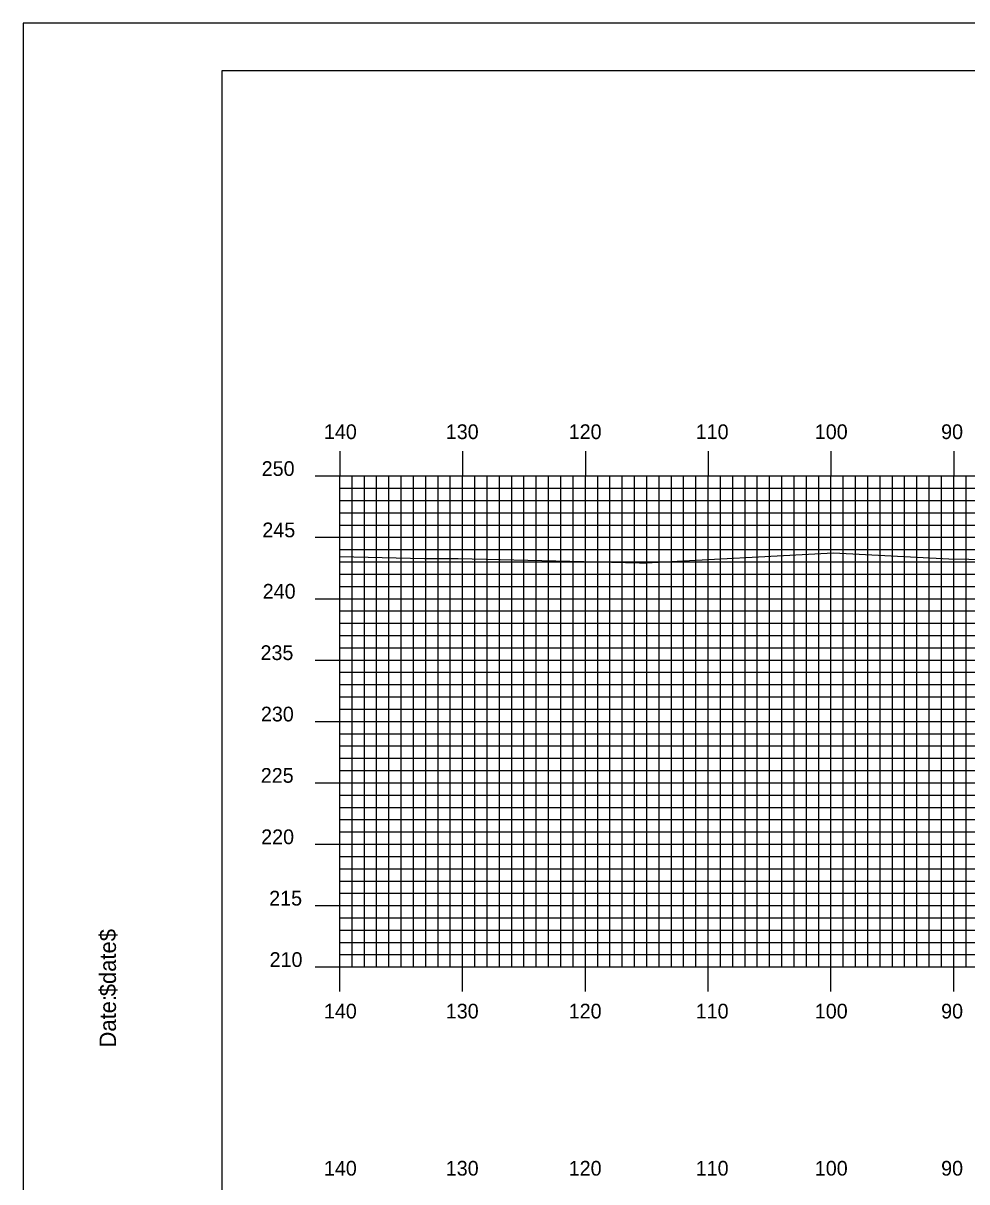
# Model space of a CAD drawing. Extents: x 1816489 to 1816833, y 442591 to 442811.
# Drawn here: x 1816489.3 to 1816566.1, y 442716.2 to 442810.5 of the extents above; entities that cross this region are included whole.
import ezdxf

# ---------------------------------------------------------------- set-up
doc = ezdxf.new("R2010")
doc.units = 0
for name, color, linetype in [('BORDER', 7, 'Continuous'), ('H_V ANNOTATION', 7, 'Continuous'), ('MAJOR', 7, 'Continuous'), ('MINOR', 7, 'Continuous'), ('PLOT BOUNDARY', 7, 'Continuous'), ('S_Roadway_Centerline', 7, 'Continuous')]:
    doc.layers.add(name, color=color, linetype=linetype)

msp = doc.modelspace()

# ---------------------------------------------------------------- linework, layer by layer
at = {"layer": 'BORDER'}
msp.add_lwpolyline([(1816505.473, 442596.665), (1816825.473, 442596.665), (1816825.473, 442806.665), (1816505.473, 442806.665)], close=True, dxfattribs=at)
at = {"layer": 'MAJOR'}
for p, q in [((1816515.073, 442775.669), (1816515.073, 442773.665)), ((1816525.073, 442775.669), (1816525.073, 442773.665)), ((1816535.073, 442775.669), (1816535.073, 442773.665)), ((1816545.073, 442775.669), (1816545.073, 442773.665)), ((1816555.073, 442775.669), (1816555.073, 442773.665)), ((1816565.073, 442775.669), (1816565.073, 442773.665)), ((1816513.069, 442773.665), (1816515.073, 442773.665)), ((1816515.073, 442773.665), (1816795.073, 442773.665)), ((1816515.073, 442733.665), (1816515.073, 442773.665)), ((1816515.073, 442733.665), (1816515.073, 442773.665)), ((1816515.073, 442773.665), (1816795.073, 442773.665)), ((1816525.073, 442733.665), (1816525.073, 442773.665)), ((1816535.073, 442733.665), (1816535.073, 442773.665)), ((1816545.073, 442733.665), (1816545.073, 442773.665)), ((1816555.073, 442733.665), (1816555.073, 442773.665)), ((1816565.073, 442733.665), (1816565.073, 442773.665)), ((1816513.069, 442768.665), (1816515.073, 442768.665)), ((1816515.073, 442768.665), (1816795.073, 442768.665)), ((1816513.069, 442763.665), (1816515.073, 442763.665)), ((1816515.073, 442763.665), (1816795.073, 442763.665)), ((1816513.069, 442758.665), (1816515.073, 442758.665)), ((1816515.073, 442758.665), (1816795.073, 442758.665)), ((1816513.069, 442753.665), (1816515.073, 442753.665)), ((1816515.073, 442753.665), (1816795.073, 442753.665)), ((1816513.069, 442748.665), (1816515.073, 442748.665)), ((1816515.073, 442748.665), (1816795.073, 442748.665)), ((1816513.069, 442743.665), (1816515.073, 442743.665)), ((1816515.073, 442743.665), (1816795.073, 442743.665)), ((1816513.069, 442738.665), (1816515.073, 442738.665)), ((1816515.073, 442738.665), (1816795.073, 442738.665)), ((1816513.069, 442733.665), (1816515.073, 442733.665)), ((1816515.073, 442733.665), (1816795.073, 442733.665)), ((1816515.073, 442733.665), (1816795.073, 442733.665)), ((1816515.073, 442731.661), (1816515.073, 442733.665)), ((1816525.073, 442731.661), (1816525.073, 442733.665)), ((1816535.073, 442731.661), (1816535.073, 442733.665)), ((1816545.073, 442731.661), (1816545.073, 442733.665)), ((1816555.073, 442731.661), (1816555.073, 442733.665)), ((1816565.073, 442731.661), (1816565.073, 442733.665))]:
    msp.add_line(p, q, dxfattribs=at)
at = {"layer": 'MINOR'}
for p, q in [((1816516.073, 442733.665), (1816516.073, 442773.665)), ((1816517.073, 442733.665), (1816517.073, 442773.665)), ((1816518.073, 442733.665), (1816518.073, 442773.665)), ((1816519.073, 442733.665), (1816519.073, 442773.665)), ((1816520.073, 442733.665), (1816520.073, 442773.665)), ((1816521.073, 442733.665), (1816521.073, 442773.665)), ((1816522.073, 442733.665), (1816522.073, 442773.665)), ((1816523.073, 442733.665), (1816523.073, 442773.665)), ((1816524.073, 442733.665), (1816524.073, 442773.665)), ((1816526.073, 442733.665), (1816526.073, 442773.665)), ((1816527.073, 442733.665), (1816527.073, 442773.665)), ((1816528.073, 442733.665), (1816528.073, 442773.665)), ((1816529.073, 442733.665), (1816529.073, 442773.665)), ((1816530.073, 442733.665), (1816530.073, 442773.665)), ((1816531.073, 442733.665), (1816531.073, 442773.665)), ((1816532.073, 442733.665), (1816532.073, 442773.665)), ((1816533.073, 442733.665), (1816533.073, 442773.665)), ((1816534.073, 442733.665), (1816534.073, 442773.665)), ((1816536.073, 442733.665), (1816536.073, 442773.665)), ((1816537.073, 442733.665), (1816537.073, 442773.665)), ((1816538.073, 442733.665), (1816538.073, 442773.665)), ((1816539.073, 442733.665), (1816539.073, 442773.665)), ((1816540.073, 442733.665), (1816540.073, 442773.665)), ((1816541.073, 442733.665), (1816541.073, 442773.665)), ((1816542.073, 442733.665), (1816542.073, 442773.665)), ((1816543.073, 442733.665), (1816543.073, 442773.665)), ((1816544.073, 442733.665), (1816544.073, 442773.665)), ((1816546.073, 442733.665), (1816546.073, 442773.665)), ((1816547.073, 442733.665), (1816547.073, 442773.665)), ((1816548.073, 442733.665), (1816548.073, 442773.665)), ((1816549.073, 442733.665), (1816549.073, 442773.665)), ((1816550.073, 442733.665), (1816550.073, 442773.665)), ((1816551.073, 442733.665), (1816551.073, 442773.665)), ((1816552.073, 442733.665), (1816552.073, 442773.665)), ((1816553.073, 442733.665), (1816553.073, 442773.665)), ((1816554.073, 442733.665), (1816554.073, 442773.665)), ((1816556.073, 442733.665), (1816556.073, 442773.665)), ((1816557.073, 442733.665), (1816557.073, 442773.665)), ((1816558.073, 442733.665), (1816558.073, 442773.665)), ((1816559.073, 442733.665), (1816559.073, 442773.665)), ((1816560.073, 442733.665), (1816560.073, 442773.665)), ((1816561.073, 442733.665), (1816561.073, 442773.665)), ((1816562.073, 442733.665), (1816562.073, 442773.665)), ((1816563.073, 442733.665), (1816563.073, 442773.665)), ((1816564.073, 442733.665), (1816564.073, 442773.665)), ((1816566.073, 442733.665), (1816566.073, 442773.665)), ((1816515.073, 442772.665), (1816795.073, 442772.665)), ((1816515.073, 442772.665), (1816517.077, 442772.665)), ((1816515.073, 442771.665), (1816795.073, 442771.665)), ((1816515.073, 442771.665), (1816517.077, 442771.665)), ((1816515.073, 442770.665), (1816795.073, 442770.665)), ((1816515.073, 442770.665), (1816517.077, 442770.665)), ((1816515.073, 442769.665), (1816795.073, 442769.665)), ((1816515.073, 442769.665), (1816517.077, 442769.665)), ((1816515.073, 442767.665), (1816795.073, 442767.665)), ((1816515.073, 442767.665), (1816517.077, 442767.665)), ((1816515.073, 442766.665), (1816795.073, 442766.665)), ((1816515.073, 442766.665), (1816517.077, 442766.665)), ((1816515.073, 442765.665), (1816795.073, 442765.665)), ((1816515.073, 442765.665), (1816517.077, 442765.665)), ((1816515.073, 442764.665), (1816795.073, 442764.665)), ((1816515.073, 442764.665), (1816517.077, 442764.665)), ((1816515.073, 442762.665), (1816795.073, 442762.665)), ((1816515.073, 442762.665), (1816517.077, 442762.665)), ((1816515.073, 442761.665), (1816795.073, 442761.665)), ((1816515.073, 442761.665), (1816517.077, 442761.665)), ((1816515.073, 442760.665), (1816795.073, 442760.665)), ((1816515.073, 442760.665), (1816517.077, 442760.665)), ((1816515.073, 442759.665), (1816795.073, 442759.665)), ((1816515.073, 442759.665), (1816517.077, 442759.665)), ((1816515.073, 442757.665), (1816795.073, 442757.665)), ((1816515.073, 442757.665), (1816517.077, 442757.665)), ((1816515.073, 442756.665), (1816795.073, 442756.665)), ((1816515.073, 442756.665), (1816517.077, 442756.665)), ((1816515.073, 442755.665), (1816795.073, 442755.665)), ((1816515.073, 442755.665), (1816517.077, 442755.665)), ((1816515.073, 442754.665), (1816795.073, 442754.665)), ((1816515.073, 442754.665), (1816517.077, 442754.665)), ((1816515.073, 442752.665), (1816795.073, 442752.665)), ((1816515.073, 442752.665), (1816517.077, 442752.665)), ((1816515.073, 442751.665), (1816795.073, 442751.665)), ((1816515.073, 442751.665), (1816517.077, 442751.665)), ((1816515.073, 442750.665), (1816795.073, 442750.665)), ((1816515.073, 442750.665), (1816517.077, 442750.665)), ((1816515.073, 442749.665), (1816795.073, 442749.665)), ((1816515.073, 442749.665), (1816517.077, 442749.665)), ((1816515.073, 442747.665), (1816795.073, 442747.665)), ((1816515.073, 442747.665), (1816517.077, 442747.665)), ((1816515.073, 442746.665), (1816795.073, 442746.665)), ((1816515.073, 442746.665), (1816517.077, 442746.665)), ((1816515.073, 442745.665), (1816795.073, 442745.665)), ((1816515.073, 442745.665), (1816517.077, 442745.665)), ((1816515.073, 442744.665), (1816795.073, 442744.665)), ((1816515.073, 442744.665), (1816517.077, 442744.665)), ((1816515.073, 442742.665), (1816795.073, 442742.665)), ((1816515.073, 442742.665), (1816517.077, 442742.665)), ((1816515.073, 442741.665), (1816795.073, 442741.665)), ((1816515.073, 442741.665), (1816517.077, 442741.665)), ((1816515.073, 442740.665), (1816795.073, 442740.665)), ((1816515.073, 442740.665), (1816517.077, 442740.665)), ((1816515.073, 442739.665), (1816795.073, 442739.665)), ((1816515.073, 442739.665), (1816517.077, 442739.665)), ((1816515.073, 442737.665), (1816795.073, 442737.665)), ((1816515.073, 442737.665), (1816517.077, 442737.665)), ((1816515.073, 442736.665), (1816795.073, 442736.665)), ((1816515.073, 442736.665), (1816517.077, 442736.665)), ((1816515.073, 442735.665), (1816795.073, 442735.665)), ((1816515.073, 442735.665), (1816517.077, 442735.665)), ((1816515.073, 442734.665), (1816795.073, 442734.665)), ((1816515.073, 442734.665), (1816517.077, 442734.665))]:
    msp.add_line(p, q, dxfattribs=at)
at = {"layer": 'PLOT BOUNDARY'}
msp.add_lwpolyline([(1816489.286, 442590.547), (1816829.286, 442590.547), (1816829.286, 442810.547), (1816489.286, 442810.547)], close=True, dxfattribs=at)
at = {"layer": 'S_Roadway_Centerline'}
msp.add_lwpolyline([(1816515.073, 442767.113), (1816521.969, 442766.937), (1816524.716, 442766.937), (1816539.489, 442766.585), (1816539.74, 442766.583), (1816539.881, 442766.577), (1816539.995, 442766.579), (1816555.282, 442767.387), (1816564.673, 442766.905), (1816572.774, 442766.787)], dxfattribs=at)

# ---------------------------------------------------------------- texts
at = {"layer": 'BORDER'}
for s, p in [('$date$', (1816496.843, 442731.275)), ('Date:', (1816496.843, 442727.099))]:
    msp.add_text(s, height=1.3392, rotation=90, dxfattribs=at).set_placement(p)
at = {"layer": 'H_V ANNOTATION'}
for s, p in [('140', (1816513.778, 442776.665)), ('130', (1816523.703, 442776.665)), ('120', (1816533.714, 442776.665)), ('110', (1816544.056, 442776.665)), ('100', (1816553.756, 442776.665)), ('90', (1816564.045, 442776.665)), ('250', (1816508.711, 442773.665)), ('245', (1816508.765, 442768.665)), ('240', (1816508.797, 442763.665)), ('235', (1816508.615, 442758.665)), ('230', (1816508.647, 442753.665)), ('225', (1816508.637, 442748.665)), ('220', (1816508.669, 442743.665)), ('215', (1816509.322, 442738.665)), ('210', (1816509.354, 442733.665)), ('140', (1816513.778, 442729.465)), ('130', (1816523.703, 442729.465)), ('120', (1816533.714, 442729.465)), ('110', (1816544.056, 442729.465)), ('100', (1816553.756, 442729.465)), ('90', (1816564.045, 442729.465)), ('140', (1816513.778, 442716.665)), ('130', (1816523.703, 442716.665)), ('120', (1816533.714, 442716.665)), ('110', (1816544.056, 442716.665)), ('100', (1816553.756, 442716.665)), ('90', (1816564.045, 442716.665))]:
    msp.add_text(s, height=1.2, dxfattribs=at).set_placement(p)
at = {"layer": 'MAJOR'}
msp.add_text('-', height=0.012, dxfattribs=at).set_placement((1816515.064, 442733.665))

doc.saveas('drawing.dxf')
